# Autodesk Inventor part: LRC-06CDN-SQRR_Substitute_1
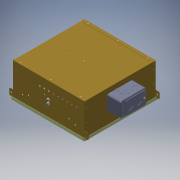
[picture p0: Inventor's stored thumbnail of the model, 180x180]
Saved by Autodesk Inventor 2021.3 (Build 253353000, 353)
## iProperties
Part Number: LRC-06CDN-SQRR_Substitute_1
Material: Generic
Document SubType Name: Modeling
Designer: JChurch
Manufacturer: Standard
Standards Organization: Custom
Density: 1 g/cm^3
Appearance: Smooth - Black
Author: JChurch
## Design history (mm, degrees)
derived "LRC-06CDN-SQRR.iam"
body "Solid9"
node "830376-01-00.iam:1::830376-PAN.ipt:1"
node "830376-01-00.iam:1::830376-FLANGE-2.ipt:2"
body "Solid10"
node "830376-01-00.iam:1::506010-00-38 SQUEEZED.ipt:1"
body "Solid11"
node "830376-01-00.iam:1::506010-00-38 SQUEEZED.ipt:2"
body "Solid12"
node "830376-01-00.iam:1::506010-00-38 SQUEEZED.ipt:3"
body "Solid13"
node "830376-01-00.iam:1::506010-00-38 SQUEEZED.ipt:4"
body "Solid14"
node "830376-01-00.iam:1::506010-00-38 SQUEEZED.ipt:5"
body "Solid15"
node "830376-01-00.iam:1::506010-00-38 SQUEEZED.ipt:6"
body "Solid16"
node "830376-01-00.iam:1::506010-00-38 SQUEEZED.ipt:7"
body "Solid17"
node "830376-01-00.iam:1::506010-00-38 SQUEEZED.ipt:8"
body "Solid18"
node "830376-01-00.iam:1::506010-00-38 SQUEEZED.ipt:9"
body "Solid19"
node "830376-01-00.iam:1::506010-00-38 SQUEEZED.ipt:10"
body "Solid20"
node "830376-01-00.iam:1::830376-FLANGE-2.ipt:3"
body "Solid21"
node "881088-00-00.iam:1::830140-00-00.ipt:1"
body "Solid22"
node "881088-00-00.iam:1::850014-00-00.iam:1::805044-00-00.ipt:1"
body "Solid23"
node "881088-00-00.iam:1::850014-00-00.iam:1::805174-00-00.ipt:1"
body "Solid24"
node "881088-00-00.iam:1::850014-00-00.iam:1::502055-00-00.ipt:1"
body "Solid25"
node "881088-00-00.iam:1::850014-00-00.iam:1::502055-00-00.ipt:2"
body "Solid26"
node "881088-00-00.iam:1::850014-00-00.iam:1::507032-00-00.ipt:1"
body "Solid27"
node "881088-00-00.iam:1::507000-00-00.ipt:1"
body "Solid28"
node "881088-00-00.iam:1::507000-00-00.ipt:2"
body "Solid29"
node "881088-00-00.iam:1::506002-00-00.ipt:1"
body "Solid30"
node "881088-00-00.iam:1::506002-00-00.ipt:2"
body "Solid31"
node "881088-00-00.iam:1::506002-00-00.ipt:3"
body "Solid32"
node "881088-00-00.iam:1::506002-00-00.ipt:4"
body "Solid33"
node "881088-00-00.iam:1::506002-00-00.ipt:5"
body "Solid34"
node "881088-00-00.iam:1::506002-00-00.ipt:6"
body "Solid35"
node "881088-00-00.iam:1::506002-00-00.ipt:7"
body "Solid36"
node "881088-00-00.iam:1::506002-00-00.ipt:8"
body "Solid37"
node "881088-00-00.iam:1::506002-00-00.ipt:9"
body "Solid38"
node "881088-00-00.iam:1::506002-00-00.ipt:10"
body "Solid39"
node "881088-00-00.iam:1::506002-00-00.ipt:11"
body "Solid40"
node "881088-00-00.iam:1::506002-00-00.ipt:12"
body "Solid41"
node "881088-00-00.iam:1::506002-00-00.ipt:13"
body "Solid42"
node "881088-00-00.iam:1::506002-00-00.ipt:14"
body "Solid43"
node "881088-00-00.iam:1::830392-01-00.iam:1::830392-00-00.ipt:1"
body "Solid44"
node "881088-00-00.iam:1::830392-01-00.iam:1::500027-00-00.ipt:1"
body "Solid45"
node "881088-00-00.iam:1::830392-01-00.iam:1::501030-00-00.ipt:1"
body "Solid46"
node "881088-00-00.iam:1::830392-01-00.iam:1::500027-00-00.ipt:2"
body "Solid47"
node "881088-00-00.iam:1::830392-01-00.iam:1::501030-00-00.ipt:2"
body "Solid48"
node "881088-00-00.iam:1::830392-01-00.iam:1::501030-00-00.ipt:3"
body "Solid49"
node "881088-00-00.iam:1::830392-01-00.iam:1::501030-00-00.ipt:4"
body "Solid50"
node "881088-00-00.iam:1::830392-01-00.iam:2::830392-00-00.ipt:1"
body "Solid51"
node "881088-00-00.iam:1::830392-01-00.iam:2::500027-00-00.ipt:1"
body "Solid52"
node "881088-00-00.iam:1::830392-01-00.iam:2::501030-00-00.ipt:1"
body "Solid53"
node "881088-00-00.iam:1::830392-01-00.iam:2::500027-00-00.ipt:2"
body "Solid54"
node "881088-00-00.iam:1::830392-01-00.iam:2::501030-00-00.ipt:2"
body "Solid55"
node "881088-00-00.iam:1::830392-01-00.iam:2::501030-00-00.ipt:3"
body "Solid56"
node "881088-00-00.iam:1::830392-01-00.iam:2::501030-00-00.ipt:4"
body "Solid57"
node "700466-00-XX.iam:1::700466-00-XX PANEL.ipt:1"
body "Solid58"
node "700466-00-XX.iam:1::700466-00-XX PANEL.ipt:2"
body "Solid59"
node "700466-00-XX.iam:1::700466-00-XX PANEL.ipt:3"
body "Solid60"
node "700466-00-XX.iam:1::700466-00-XX PANEL.ipt:4"
body "Solid61"
node "725267-00-00.ipt:1"
body "Solid62"
other parameters: "d15" = 61.595, "d16" = 9.525, "d17" = 9.525, "d35" = 5.08
